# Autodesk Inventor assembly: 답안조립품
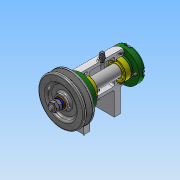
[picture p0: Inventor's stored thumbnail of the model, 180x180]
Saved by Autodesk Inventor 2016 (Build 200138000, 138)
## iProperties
Created: 2018-05
Part Number: 답안조립품
Document SubType Name: Assembly
Designer: Administrator
Author: Administrator
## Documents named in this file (16)
- C:\Users\Administrator\Desktop\480507V1028\답안조립품.iam
- C:\Users\Administrator\Desktop\480507V1028\본체-01.ipt
- C:\Users\Administrator\Desktop\480507V1028\뒤커버.ipt
- C:\Users\Administrator\Desktop\480507V1028\볼트 M4x12.ipt
- C:\Users\Administrator\Desktop\480507V1028\베어링 6002.ipt
- C:\Users\Administrator\Desktop\480507V1028\축.ipt
- C:\Users\Administrator\Desktop\480507V1028\키 3x3x12.ipt
- C:\Users\Administrator\Desktop\480507V1028\앞커버.ipt
- C:\Users\Administrator\Desktop\480507V1028\V벨트풀리.ipt
- C:\Users\Administrator\Desktop\480507V1028\와셔 8x17.ipt
- C:\Users\Administrator\Desktop\480507V1028\스프링와셔 8.ipt
- C:\Users\Administrator\Desktop\480507V1028\너트 M8.ipt
- C:\Users\Administrator\Desktop\480507V1028\니플 M6x0.75.ipt
- C:\Users\Administrator\Desktop\480507V1028\오일 실 15 25 7.ipt
- C:\Users\Administrator\Desktop\480507V1028\와셔 6x11.5.ipt
- C:\Users\Administrator\Desktop\480507V1028\볼트 M6x8.ipt
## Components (1 placed, 1 different names)
1. V벨트풀리:1
